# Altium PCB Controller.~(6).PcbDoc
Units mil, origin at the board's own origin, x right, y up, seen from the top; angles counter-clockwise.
Board outline 4000 x 2400 mil, 2 copper layers (Top Layer, Bottom Layer); 7 components, 6 nets, 17 pads, 0 vias.
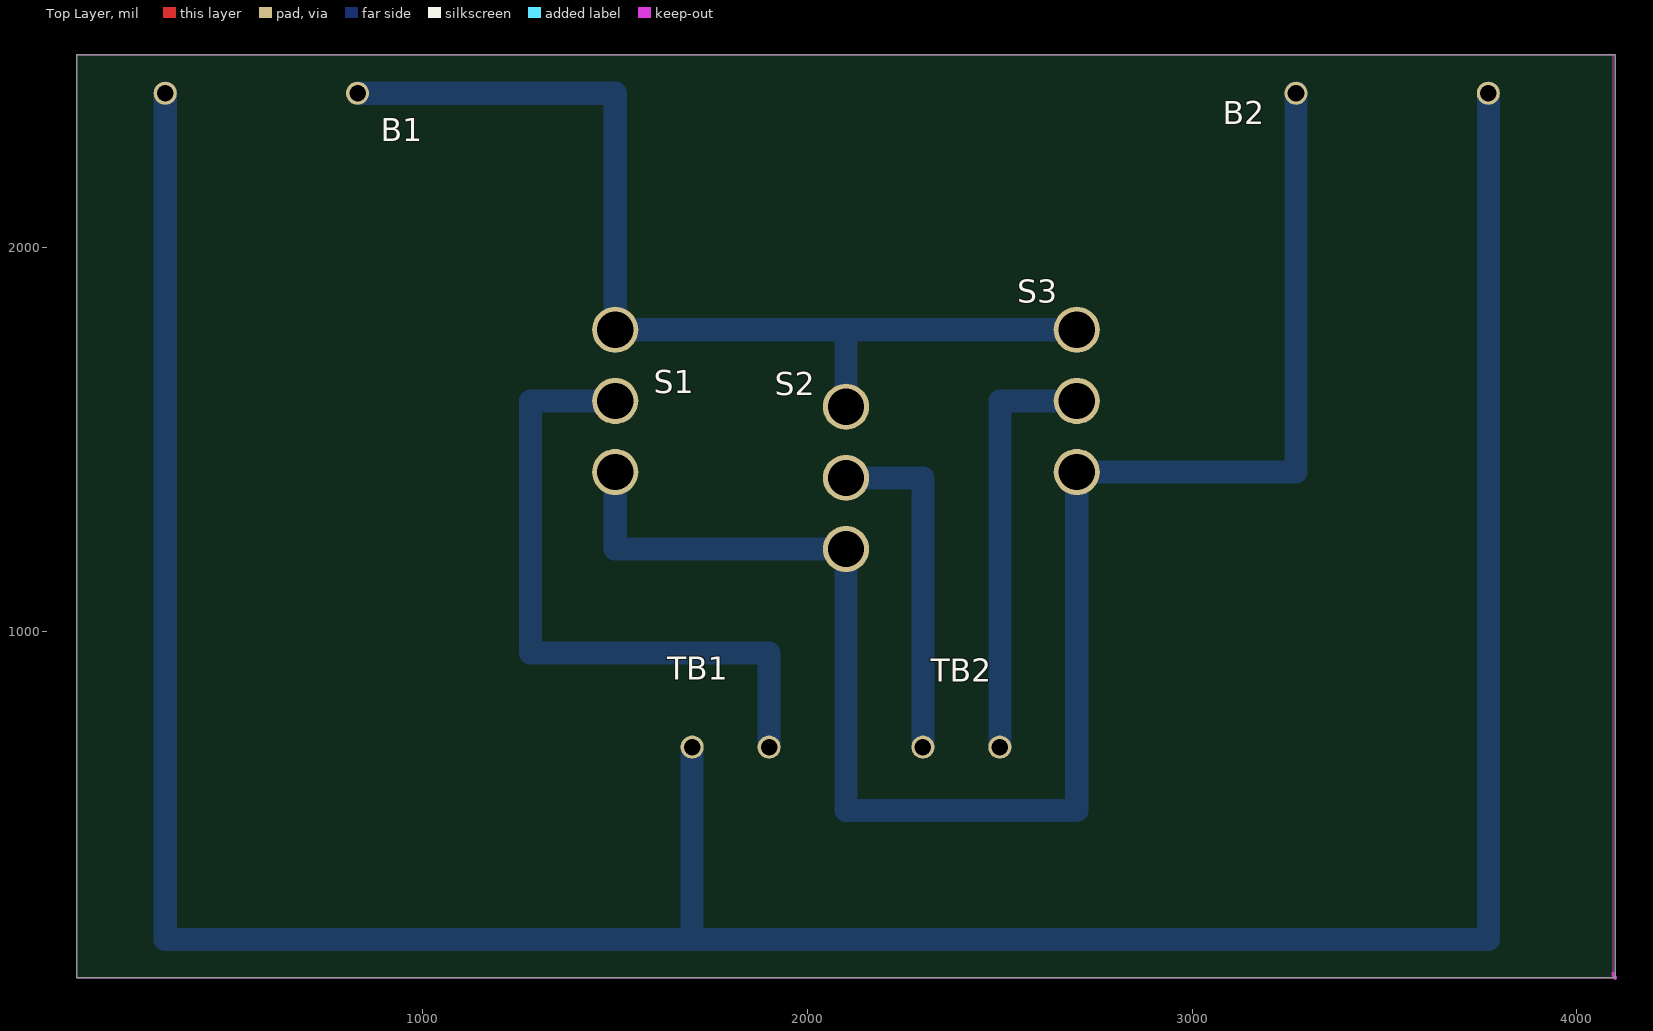
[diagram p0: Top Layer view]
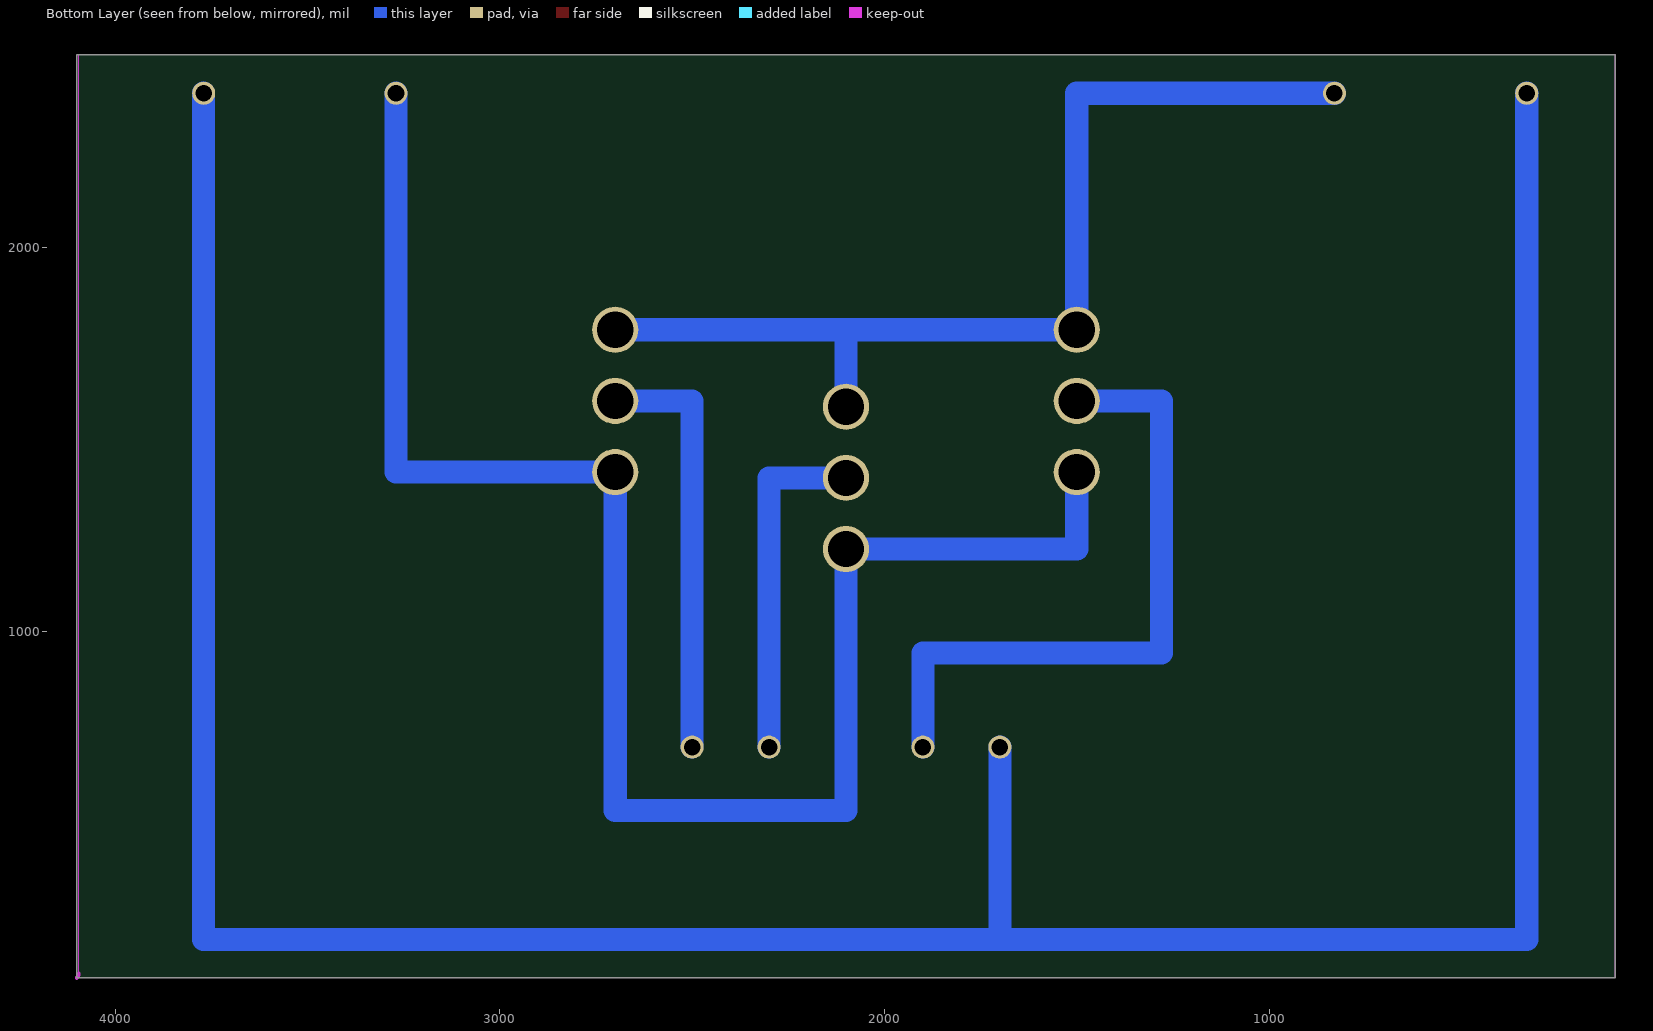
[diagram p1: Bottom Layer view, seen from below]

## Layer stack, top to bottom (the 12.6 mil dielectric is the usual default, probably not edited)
Top Layer: signal copper 1.4
Dielectric: dielectric 12.6, FR-4, Dk 4.8
Bottom Layer: signal copper 1.4

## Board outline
100,100 4100,100 4100,2500 100,2500

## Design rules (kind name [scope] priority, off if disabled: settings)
Clearance [All] p1: gap=10
PolygonConnect [All] p1: connectstyle=Relief reliefconductorwidth=10 reliefentries=4 polygonreliefangle="90 Angle"
RoomDefinition Controller [InComponentClass('Controller')] p1: confinementstyle=ConfineIn formatcopy=TRUE lockcomponents=FALSE outline 95,95 4105,95 4105,2505 95,2505
RoutingVias [All] p1: holewidth=28 width=50 viastyle="Through Hole" minholewidth=28 minwidth=50 maxholewidth=28 maxwidth=50
SilkscreenOverComponentPads [All] p1: minsilkscreentomaskgap=10
SolderMaskExpansion [All] p1: expansion=4
Width [All] p1: maxlimit=60 minlimit=10 preferedwidth=10 minimp=50.000000 maximp=50.000000 favimp=50.000000
27 further rules are at their usual default settings.

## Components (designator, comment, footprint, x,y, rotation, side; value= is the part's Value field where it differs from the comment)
B1 "Bat, 2xAA" BAT1 580,2400 r180 top
B2 "Bat, 2xAA" BAT1 3520,2400 r180 top
S1 "SW-SPDT" "SWITCH, SPDT, SOLDER LUG" 1500,1600 r90 top
S2 "SW-SPDT" "SWITCH, SPDT, SOLDER LUG" 2100,1400 r90 top
S3 "SW-SPDT" "SWITCH, SPDT, SOLDER LUG" 2700,1600 r90 top
TB1 "TB1x2" TB1X2 1800,700 r0 top
TB2 "TB1x2" TB1X2 2400,700 r0 top

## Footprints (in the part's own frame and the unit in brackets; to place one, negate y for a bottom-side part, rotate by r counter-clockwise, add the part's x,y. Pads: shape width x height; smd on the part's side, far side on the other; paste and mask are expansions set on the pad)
BAT1 [mil] "Battery Holder 2xAA"
  round 60 hole 43: +(-250,0) -(250,0)
"SWITCH, SPDT, SOLDER LUG" [mil]
  round 120 hole 94: 1(-185,0) 2(0,0) 3(185,0)
TB1X2 [mil]
  round 60 hole 43: 1(-100,0) 2(100,0)

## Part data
S1 S2 S3: "SPDT Subminiature Toggle Switch, Right Angle Mounting, Vertical Actuation"

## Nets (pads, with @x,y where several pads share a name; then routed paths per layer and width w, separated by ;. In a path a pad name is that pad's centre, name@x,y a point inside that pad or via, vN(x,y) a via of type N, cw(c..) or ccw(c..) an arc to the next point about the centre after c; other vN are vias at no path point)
NetB1_+: B1.+ S1.3 S2.3 S3.3 | length 2685
  Bottom Layer w60: B1.+ 1500,2400 S1.3 2100,1785 ; S2.3 2100,1785 ; S3.3 2100,1785
NetB1_-: B1.- B2.+ TB1.1 | length 8355
  Bottom Layer w10: TB1.1@1685,700 TB1.1
  Bottom Layer w60: B1.- 330,200 1700,200 ; TB1.1 1700,200 ; B2.+ 3770,200 1700,200
NetB2_-: B2.- S1.1 S2.1 S3.1 | length 4515
  Bottom Layer w60: S1.1 1500,1215 S2.1 2100,535 2700,535 S3.1 3270,1415 B2.-
NetS1_2: S1.2 TB1.2 | length 1740
  Bottom Layer w60: S1.2 1280,1600 1280,945 1900,945 TB1.2
NetS2_2: S2.2 TB2.1 | length 900
  Bottom Layer w60: S2.2 2300,1400 TB2.1
NetS3_2: S3.2 TB2.2 | length 1100
  Bottom Layer w60: TB2.2 2500,1600 S3.2

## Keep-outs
Keep-Out Layer:
  lines w1: 4095,112.07 4095,2500 100,2500 100,100 4100,100
  lines w10: 4095,112.07 ccw(c4112.07,112.07) 4100,100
